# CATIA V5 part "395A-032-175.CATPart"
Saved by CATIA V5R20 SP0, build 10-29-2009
Part number: 395A-032-175
Source: Unknown
Property "ARTICLENO": "395A-032-175"
Property "B": "9"
Property "BOMINFO": "395A-032-175"
Property "C": "10.000"
Property "CODE": "395A-032-175"
Property "D": "32.000"
Property "D1": "40.000"
Property "D2": "3x10"
Property "D3": "13"
Property "D5": "24"
Property "D6": "21.000"
Property "H": "4.000"
Property "L": "175.000"
Property "L1": "10.000"
Property "L2": "145.000"
Property "L3": "9.000"
Property "L4": "10"
Property "LINA": "395A-032-175"
Property "M": "10.000"
Property "M1": "10.000"
Property "M2": "10.000"
Property "MAXLOAD": "3200 Kg"
Property "MDW": "6400 Kg"
Property "NB": "395A-032-175"
Property "NBSYN": "$CODE."
Property "NN": "395A"
Property "NT": "Pin"
Property "P": "5"
Property "S": "9.000"
Property "SUPPLIER": "CF"
Bounding box of the stored display mesh (mm): x 0 to 175, y -20 to 20, z -20 to 20
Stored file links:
  C:\Users\Utente\Desktop\3D files 395A\395A-032-175.CATPart
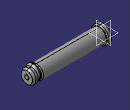
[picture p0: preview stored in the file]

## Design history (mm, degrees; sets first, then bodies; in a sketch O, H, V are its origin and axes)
Body1 "Geometry.1" (main body)
  Solid1 "395A-032-175.catpart": solid without history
